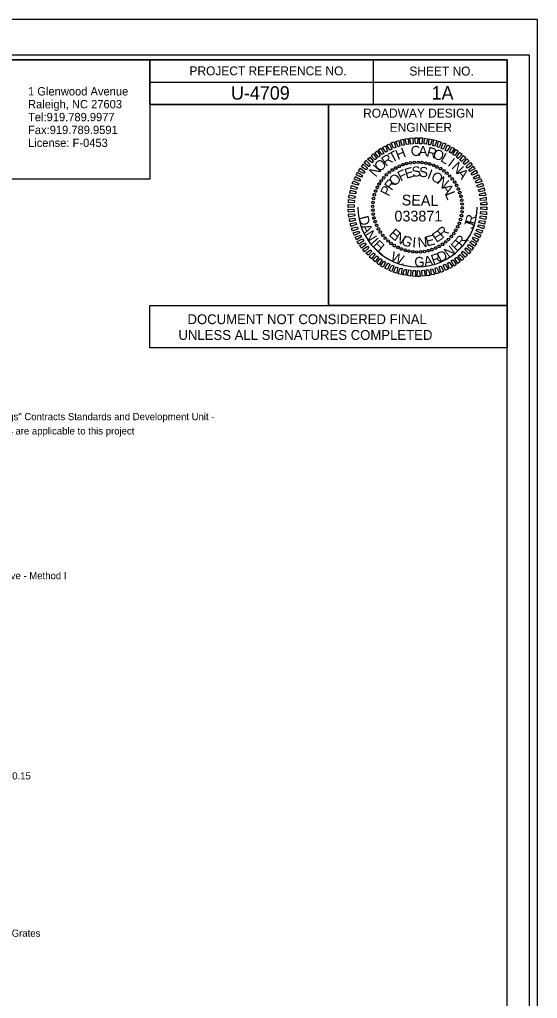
# Model space of a CAD drawing. Extents: x 1537922 to 1539606, y 409903 to 410998.
# Drawn here: x 1539316 to 1539606, y 410451 to 410998 of the extents above; entities that cross this region are included whole.
import ezdxf

# ---------------------------------------------------------------- set-up
doc = ezdxf.new("R2010")
doc.units = 0
for name, color, linetype in [('Old_Level_1', 7, 'Continuous'), ('Old_Level_2', 7, 'Continuous'), ('Old_Level_58', 7, 'Continuous'), ('Scratch_Level_0', 7, 'Continuous'), ('Sheet Cutting Line CELL', 7, 'Continuous'), ('Sheet Data Field CELL', 7, 'Continuous'), ('Sheet Plan CELL', 7, 'Continuous'), ('Sheet Plot Border Inside CELL', 7, 'Continuous'), ('Sheet Plot Border Outside CELL', 7, 'Continuous'), ('Sheet Professional Seal CELL', 7, 'Continuous'), ('Sheet Profile Grid Minor CELL', 7, 'Continuous'), ('Sheet Sticker Exception Certification CELL', 7, 'Continuous')]:
    doc.layers.add(name, color=color, linetype=linetype)

msp = doc.modelspace()

# ---------------------------------------------------------------- linework, layer by layer
at = {"layer": 'Old_Level_58'}
msp.add_lwpolyline([(1539188.77, 410975.85), (1539388.82, 410975.85), (1539388.82, 410909.16), (1539188.77, 410909.16)], close=True, dxfattribs=at)
at = {"layer": 'Scratch_Level_0'}
msp.add_arc((1539538.69, 410893.42), 33.36, 180, 360, dxfattribs=at)
at = {"layer": 'Sheet Cutting Line CELL'}
msp.add_line((1539605.87, 410998.35), (1537922.37, 410998.35), dxfattribs=at)
at = {"layer": 'Sheet Plan CELL'}
for p, q in [((1539513.87, 410975.8), (1539513.87, 410950.8)), ((1539388.82, 410963.3), (1539588.87, 410963.3)), ((1539388.82, 410950.8), (1539588.87, 410950.8)), ((1539388.82, 410950.8), (1539588.87, 410950.8)), ((1539488.87, 410950.8), (1539488.87, 410838.35))]:
    msp.add_line(p, q, dxfattribs=at)
for points in [[(1539588.87, 410975.85), (1538088.87, 410975.85), (1538088.87, 409925.85), (1539588.87, 409925.85)], [(1539388.82, 410975.85), (1539588.87, 410975.85), (1539588.87, 410950.8), (1539388.82, 410950.8)], [(1539488.87, 410950.8), (1539588.87, 410950.8), (1539588.87, 410838.3), (1539488.87, 410838.3)]]:
    msp.add_lwpolyline(points, close=True, dxfattribs=at)
at = {"layer": 'Sheet Plot Border Inside CELL'}
msp.add_lwpolyline([(1537935.37, 409923.35), (1539601.37, 409923.35), (1539601.37, 410978.35), (1537935.37, 410978.35)], close=True, dxfattribs=at)
at = {"layer": 'Sheet Plot Border Outside CELL'}
msp.add_lwpolyline([(1537922.37, 409903.35), (1539605.87, 409903.35), (1539605.87, 410998.35), (1537922.37, 410998.35)], close=True, dxfattribs=at)
at = {"layer": 'Sheet Professional Seal CELL'}
for p, q in [((1539528.49, 410916.37), (1539528.49, 410916.37)), ((1539530.49, 410917.17), (1539530.49, 410917.17)), ((1539532.59, 410917.77), (1539532.59, 410917.77)), ((1539534.79, 410918.17), (1539534.79, 410918.17)), ((1539536.94, 410918.47), (1539536.94, 410918.47)), ((1539539.14, 410918.52), (1539539.14, 410918.52)), ((1539541.34, 410918.37), (1539541.34, 410918.37)), ((1539543.49, 410918.02), (1539543.49, 410918.02)), ((1539545.59, 410917.57), (1539545.59, 410917.57)), ((1539547.69, 410916.87), (1539547.69, 410916.87)), ((1539549.69, 410915.97), (1539549.69, 410915.97)), ((1539521.24, 410911.47), (1539521.24, 410911.47)), ((1539522.89, 410912.97), (1539522.89, 410912.97)), ((1539524.64, 410914.22), (1539524.64, 410914.22)), ((1539526.54, 410915.37), (1539526.54, 410915.37)), ((1539551.64, 410914.97), (1539551.64, 410914.97)), ((1539553.44, 410913.72), (1539553.44, 410913.72)), ((1539555.19, 410912.37), (1539555.19, 410912.37)), ((1539556.74, 410910.87), (1539556.74, 410910.87)), ((1539517.14, 410906.37), (1539517.14, 410906.37)), ((1539518.39, 410908.17), (1539518.39, 410908.17)), ((1539519.74, 410909.92), (1539519.74, 410909.92)), ((1539558.24, 410909.22), (1539558.24, 410909.22)), ((1539559.49, 410907.47), (1539559.49, 410907.47)), ((1539560.64, 410905.57), (1539560.64, 410905.57)), ((1539514.54, 410900.32), (1539514.54, 410900.32)), ((1539515.24, 410902.42), (1539515.24, 410902.42)), ((1539516.14, 410904.42), (1539516.14, 410904.42)), ((1539561.64, 410903.62), (1539561.64, 410903.62)), ((1539562.44, 410901.62), (1539562.44, 410901.62)), ((1539563.04, 410899.52), (1539563.04, 410899.52)), ((1539513.59, 410893.87), (1539513.59, 410893.87)), ((1539513.74, 410896.07), (1539513.74, 410896.07)), ((1539514.09, 410898.22), (1539514.09, 410898.22)), ((1539563.44, 410897.32), (1539563.44, 410897.32)), ((1539563.74, 410895.17), (1539563.74, 410895.17)), ((1539513.64, 410891.67), (1539513.64, 410891.67)), ((1539513.94, 410889.52), (1539513.94, 410889.52)), ((1539538.69, 410893.42), (1539538.69, 410893.42)), ((1539563.29, 410888.62), (1539563.29, 410888.62)), ((1539563.64, 410890.77), (1539563.64, 410890.77)), ((1539563.79, 410892.97), (1539563.79, 410892.97)), ((1539514.34, 410887.32), (1539514.34, 410887.32)), ((1539514.94, 410885.22), (1539514.94, 410885.22)), ((1539515.74, 410883.22), (1539515.74, 410883.22)), ((1539562.14, 410884.42), (1539562.14, 410884.42)), ((1539562.84, 410886.52), (1539562.84, 410886.52)), ((1539516.74, 410881.27), (1539516.74, 410881.27)), ((1539517.89, 410879.37), (1539517.89, 410879.37)), ((1539519.14, 410877.62), (1539519.14, 410877.62)), ((1539558.99, 410878.67), (1539558.99, 410878.67)), ((1539560.24, 410880.47), (1539560.24, 410880.47)), ((1539561.24, 410882.42), (1539561.24, 410882.42)), ((1539520.64, 410875.97), (1539520.64, 410875.97)), ((1539522.19, 410874.47), (1539522.19, 410874.47)), ((1539523.94, 410873.12), (1539523.94, 410873.12)), ((1539525.74, 410871.87), (1539525.74, 410871.87)), ((1539552.74, 410872.62), (1539552.74, 410872.62)), ((1539554.49, 410873.87), (1539554.49, 410873.87)), ((1539556.14, 410875.37), (1539556.14, 410875.37)), ((1539557.64, 410876.92), (1539557.64, 410876.92)), ((1539527.69, 410870.87), (1539527.69, 410870.87)), ((1539529.69, 410869.97), (1539529.69, 410869.97)), ((1539531.79, 410869.27), (1539531.79, 410869.27)), ((1539533.89, 410868.82), (1539533.89, 410868.82)), ((1539536.04, 410868.47), (1539536.04, 410868.47)), ((1539538.24, 410868.32), (1539538.24, 410868.32)), ((1539540.44, 410868.37), (1539540.44, 410868.37)), ((1539542.59, 410868.67), (1539542.59, 410868.67)), ((1539544.79, 410869.07), (1539544.79, 410869.07)), ((1539546.89, 410869.67), (1539546.89, 410869.67)), ((1539548.89, 410870.47), (1539548.89, 410870.47)), ((1539550.84, 410871.47), (1539550.84, 410871.47))]:
    msp.add_line(p, q, dxfattribs=at)
for points in [[(1539534.99, 410928.72), (1539534.44, 410931.92), (1539536.14, 410932.12), (1539536.19, 410928.87)], [(1539537.49, 410928.97), (1539537.24, 410932.22), (1539538.89, 410932.17), (1539538.69, 410928.92)], [(1539539.89, 410928.92), (1539539.89, 410932.17), (1539541.54, 410932.12), (1539541.09, 410928.87)], [(1539542.39, 410928.77), (1539542.59, 410932.02), (1539544.24, 410931.72), (1539543.59, 410928.57)], [(1539520.99, 410924.17), (1539519.14, 410926.87), (1539520.69, 410927.67), (1539521.94, 410924.77)], [(1539523.14, 410925.37), (1539521.54, 410928.17), (1539523.09, 410928.87), (1539524.24, 410925.82)], [(1539525.34, 410926.42), (1539524.04, 410929.32), (1539525.54, 410929.92), (1539526.59, 410926.72)], [(1539527.79, 410927.22), (1539526.64, 410930.22), (1539528.19, 410930.67), (1539528.84, 410927.57)], [(1539530.19, 410927.87), (1539529.14, 410931.02), (1539530.84, 410931.37), (1539531.24, 410928.12)], [(1539532.59, 410928.42), (1539531.79, 410931.62), (1539533.44, 410931.77), (1539533.79, 410928.57)], [(1539544.79, 410928.37), (1539545.24, 410931.57), (1539546.89, 410931.32), (1539545.99, 410928.22)], [(1539547.34, 410927.82), (1539547.84, 410931.07), (1539549.54, 410930.67), (1539548.39, 410927.57)], [(1539549.74, 410927.17), (1539550.49, 410930.27), (1539552.04, 410929.77), (1539550.79, 410926.82)], [(1539551.99, 410926.27), (1539553.14, 410929.42), (1539554.54, 410928.82), (1539553.14, 410925.92)], [(1539554.24, 410925.32), (1539555.49, 410928.27), (1539557.04, 410927.57), (1539555.34, 410924.77)], [(1539556.54, 410924.17), (1539557.89, 410927.02), (1539559.39, 410926.17), (1539557.49, 410923.57)], [(1539513.24, 410918.12), (1539510.69, 410920.17), (1539511.94, 410921.32), (1539514.04, 410918.92)], [(1539514.89, 410919.87), (1539512.69, 410922.07), (1539513.89, 410923.27), (1539515.84, 410920.57)], [(1539516.89, 410921.42), (1539514.74, 410923.82), (1539516.09, 410924.87), (1539517.84, 410922.07)], [(1539518.79, 410922.92), (1539516.94, 410925.47), (1539518.24, 410926.42), (1539519.89, 410923.52)], [(1539558.49, 410922.82), (1539560.24, 410925.72), (1539561.54, 410924.67), (1539559.59, 410922.22)], [(1539560.54, 410921.32), (1539562.39, 410924.07), (1539563.69, 410922.97), (1539561.49, 410920.62)], [(1539562.44, 410919.77), (1539564.49, 410922.37), (1539565.69, 410921.17), (1539563.39, 410919.02)], [(1539509.99, 410914.32), (1539507.29, 410916.02), (1539508.24, 410917.47), (1539510.64, 410915.27)], [(1539511.49, 410916.22), (1539508.89, 410918.17), (1539509.99, 410919.47), (1539512.19, 410917.12)], [(1539564.24, 410918.02), (1539566.39, 410920.37), (1539567.59, 410919.17), (1539564.99, 410917.22)], [(1539565.99, 410916.22), (1539568.29, 410918.47), (1539569.34, 410917.12), (1539566.69, 410915.22)], [(1539567.49, 410914.27), (1539569.94, 410916.37), (1539570.89, 410914.92), (1539568.09, 410913.32)], [(1539506.29, 410907.87), (1539503.19, 410909.02), (1539503.94, 410910.57), (1539506.79, 410908.97)], [(1539507.29, 410910.17), (1539504.44, 410911.42), (1539505.19, 410912.97), (1539507.89, 410911.12)], [(1539508.49, 410912.32), (1539505.69, 410913.82), (1539506.69, 410915.22), (1539509.29, 410913.22)], [(1539568.79, 410912.22), (1539571.44, 410914.12), (1539572.39, 410912.62), (1539569.49, 410911.22)], [(1539570.09, 410910.02), (1539572.89, 410911.77), (1539573.54, 410910.22), (1539570.69, 410909.07)], [(1539504.54, 410903.27), (1539501.44, 410903.92), (1539501.79, 410905.57), (1539504.94, 410904.32)], [(1539505.29, 410905.67), (1539502.19, 410906.57), (1539502.84, 410908.12), (1539505.84, 410906.72)], [(1539571.09, 410907.87), (1539574.04, 410909.37), (1539574.69, 410907.77), (1539571.59, 410906.77)], [(1539571.99, 410905.52), (1539575.04, 410906.82), (1539575.59, 410905.27), (1539572.49, 410904.47)], [(1539503.49, 410898.32), (1539500.29, 410898.62), (1539500.49, 410900.32), (1539503.74, 410899.52)], [(1539503.89, 410900.87), (1539500.79, 410901.27), (1539501.14, 410902.97), (1539504.29, 410901.92)], [(1539572.79, 410903.12), (1539575.99, 410904.27), (1539576.29, 410902.62), (1539573.14, 410902.07)], [(1539573.39, 410900.72), (1539576.54, 410901.67), (1539576.84, 410899.97), (1539573.69, 410899.67)], [(1539503.19, 410893.42), (1539499.94, 410893.27), (1539499.94, 410894.97), (1539503.19, 410894.62)], [(1539503.24, 410895.92), (1539499.99, 410896.02), (1539500.09, 410897.67), (1539503.34, 410897.12)], [(1539573.84, 410898.32), (1539577.09, 410899.02), (1539577.24, 410897.32), (1539574.04, 410897.12)], [(1539574.14, 410895.92), (1539577.39, 410896.32), (1539577.49, 410894.62), (1539574.24, 410894.72)], [(1539503.24, 410890.92), (1539499.99, 410890.52), (1539499.89, 410892.22), (1539503.14, 410892.12)], [(1539503.54, 410888.52), (1539500.29, 410887.82), (1539500.14, 410889.52), (1539503.34, 410889.72)], [(1539573.89, 410888.52), (1539577.09, 410888.22), (1539576.89, 410886.52), (1539573.64, 410887.32)], [(1539574.14, 410890.92), (1539577.39, 410890.82), (1539577.29, 410889.17), (1539574.04, 410889.72)], [(1539574.19, 410893.42), (1539577.44, 410893.57), (1539577.44, 410891.87), (1539574.19, 410892.22)], [(1539503.99, 410886.12), (1539500.84, 410885.17), (1539500.54, 410886.87), (1539503.69, 410887.17)], [(1539504.59, 410883.72), (1539501.39, 410882.57), (1539501.09, 410884.22), (1539504.24, 410884.77)], [(1539572.84, 410883.57), (1539575.94, 410882.92), (1539575.59, 410881.27), (1539572.44, 410882.52)], [(1539573.49, 410885.97), (1539576.59, 410885.57), (1539576.24, 410883.87), (1539573.09, 410884.92)], [(1539505.39, 410881.32), (1539502.34, 410880.02), (1539501.79, 410881.57), (1539504.89, 410882.37)], [(1539506.29, 410878.97), (1539503.34, 410877.47), (1539502.69, 410879.07), (1539505.79, 410880.07)], [(1539507.29, 410876.82), (1539504.49, 410875.07), (1539503.84, 410876.62), (1539506.69, 410877.77)], [(1539571.09, 410878.97), (1539574.19, 410877.82), (1539573.44, 410876.27), (1539570.59, 410877.87)], [(1539572.09, 410881.17), (1539575.19, 410880.27), (1539574.54, 410878.72), (1539571.54, 410880.12)], [(1539508.59, 410874.62), (1539505.94, 410872.72), (1539504.99, 410874.22), (1539507.89, 410875.62)], [(1539509.89, 410872.57), (1539507.44, 410870.47), (1539506.49, 410871.92), (1539509.29, 410873.52)], [(1539567.39, 410872.52), (1539570.09, 410870.82), (1539569.14, 410869.37), (1539566.74, 410871.57)], [(1539568.89, 410874.52), (1539571.69, 410873.02), (1539570.69, 410871.62), (1539568.09, 410873.62)], [(1539570.09, 410876.67), (1539572.94, 410875.42), (1539572.19, 410873.87), (1539569.49, 410875.72)], [(1539511.39, 410870.62), (1539509.09, 410868.37), (1539508.04, 410869.72), (1539510.69, 410871.62)], [(1539513.14, 410868.82), (1539510.99, 410866.47), (1539509.79, 410867.67), (1539512.39, 410869.62)], [(1539514.94, 410867.07), (1539512.89, 410864.47), (1539511.69, 410865.67), (1539513.99, 410867.82)], [(1539562.49, 410866.97), (1539564.69, 410864.77), (1539563.49, 410863.57), (1539561.54, 410866.27)], [(1539564.14, 410868.72), (1539566.69, 410866.67), (1539565.44, 410865.52), (1539563.34, 410867.92)], [(1539565.89, 410870.62), (1539568.49, 410868.67), (1539567.39, 410867.37), (1539565.19, 410869.72)], [(1539516.84, 410865.52), (1539514.99, 410862.77), (1539513.69, 410863.87), (1539515.89, 410866.22)], [(1539518.89, 410864.02), (1539517.14, 410861.12), (1539515.84, 410862.17), (1539517.79, 410864.62)], [(1539520.84, 410862.67), (1539519.49, 410859.82), (1539517.99, 410860.67), (1539519.89, 410863.27)], [(1539523.14, 410861.52), (1539521.89, 410858.57), (1539520.34, 410859.27), (1539522.04, 410862.07)], [(1539525.39, 410860.57), (1539524.24, 410857.42), (1539522.84, 410858.02), (1539524.24, 410860.92)], [(1539554.24, 410861.47), (1539555.84, 410858.67), (1539554.29, 410857.97), (1539553.14, 410861.02)], [(1539556.39, 410862.67), (1539558.24, 410859.97), (1539556.69, 410859.17), (1539555.44, 410862.07)], [(1539558.59, 410863.92), (1539560.44, 410861.37), (1539559.14, 410860.42), (1539557.49, 410863.32)], [(1539560.49, 410865.42), (1539562.64, 410863.02), (1539561.29, 410861.97), (1539559.54, 410864.77)], [(1539527.64, 410859.67), (1539526.89, 410856.57), (1539525.34, 410857.07), (1539526.59, 410860.02)], [(1539530.04, 410859.02), (1539529.54, 410855.77), (1539527.84, 410856.17), (1539528.99, 410859.27)], [(1539532.59, 410858.47), (1539532.14, 410855.27), (1539530.49, 410855.52), (1539531.39, 410858.62)], [(1539534.99, 410858.07), (1539534.79, 410854.82), (1539533.14, 410855.12), (1539533.79, 410858.27)], [(1539537.49, 410857.92), (1539537.49, 410854.67), (1539535.84, 410854.72), (1539536.29, 410857.97)], [(1539539.89, 410857.87), (1539540.14, 410854.62), (1539538.49, 410854.67), (1539538.69, 410857.92)], [(1539542.39, 410858.12), (1539542.94, 410854.92), (1539541.24, 410854.72), (1539541.19, 410857.97)], [(1539544.79, 410858.42), (1539545.59, 410855.22), (1539543.94, 410855.07), (1539543.59, 410858.27)], [(1539547.19, 410858.97), (1539548.24, 410855.82), (1539546.54, 410855.47), (1539546.14, 410858.72)], [(1539549.59, 410859.62), (1539550.74, 410856.62), (1539549.19, 410856.17), (1539548.54, 410859.27)], [(1539552.04, 410860.42), (1539553.34, 410857.52), (1539551.84, 410856.92), (1539550.79, 410860.12)]]:
    msp.add_lwpolyline(points, close=True, dxfattribs=at)
for centre, major_axis in [((1539526.53, 410915.36), (-0.349, 0.63)), ((1539528.49, 410916.33), (-0.293, 0.658)), ((1539530.52, 410917.13), (-0.234, 0.681)), ((1539532.62, 410917.76), (-0.174, 0.699)), ((1539534.77, 410918.19), (-0.113, 0.711)), ((1539536.94, 410918.44), (-0.05, 0.718)), ((1539539.13, 410918.5), (0.013, 0.72)), ((1539541.31, 410918.36), (0.075, 0.716)), ((1539543.48, 410918.04), (0.137, 0.707)), ((1539545.6, 410917.53), (0.198, 0.692)), ((1539547.68, 410916.84), (0.258, 0.672)), ((1539549.68, 410915.96), (0.316, 0.647)), ((1539551.61, 410914.92), (0.371, 0.617)), ((1539519.76, 410909.88), (-0.543, 0.472)), ((1539521.27, 410911.46), (-0.5, 0.518)), ((1539522.91, 410912.91), (-0.453, 0.56)), ((1539524.67, 410914.21), (-0.403, 0.597)), ((1539553.43, 410913.71), (0.423, 0.582)), ((1539555.14, 410912.35), (0.472, 0.543)), ((1539556.73, 410910.84), (0.518, 0.5)), ((1539516.15, 410904.42), (-0.647, 0.316)), ((1539517.19, 410906.34), (-0.617, 0.371)), ((1539518.4, 410908.16), (-0.582, 0.423)), ((1539558.18, 410909.2), (0.56, 0.453)), ((1539559.48, 410907.45), (0.597, 0.403)), ((1539560.63, 410905.58), (0.63, 0.349)), ((1539514.58, 410900.33), (-0.692, 0.198)), ((1539515.28, 410902.41), (-0.672, 0.258)), ((1539561.6, 410903.62), (0.658, 0.293)), ((1539562.4, 410901.59), (0.681, 0.234)), ((1539563.02, 410899.49), (0.699, 0.174)), ((1539513.61, 410893.86), (-0.72, 0.013)), ((1539513.75, 410896.04), (-0.716, 0.075)), ((1539514.07, 410898.21), (-0.707, 0.137)), ((1539563.46, 410897.34), (0.711, 0.113)), ((1539563.71, 410895.17), (0.718, 0.05)), ((1539563.77, 410892.98), (0.72, -0.013)), ((1539513.67, 410891.67), (-0.718, -0.05)), ((1539513.92, 410889.5), (-0.711, -0.113)), ((1539563.31, 410888.64), (0.707, -0.137)), ((1539563.63, 410890.8), (0.716, -0.075)), ((1539514.35, 410887.35), (-0.699, -0.174)), ((1539514.98, 410885.26), (-0.681, -0.234)), ((1539515.78, 410883.22), (-0.658, -0.293)), ((1539561.23, 410882.43), (0.647, -0.316)), ((1539562.1, 410884.43), (0.672, -0.258)), ((1539562.8, 410886.51), (0.692, -0.198)), ((1539516.75, 410881.26), (-0.63, -0.349)), ((1539517.9, 410879.4), (-0.597, -0.403)), ((1539519.2, 410877.64), (-0.56, -0.453)), ((1539557.62, 410876.97), (0.543, -0.472)), ((1539558.98, 410878.68), (0.582, -0.423)), ((1539560.19, 410880.5), (0.617, -0.371)), ((1539520.65, 410876), (-0.518, -0.5)), ((1539522.24, 410874.49), (-0.472, -0.543)), ((1539523.95, 410873.13), (-0.423, -0.582)), ((1539525.77, 410871.92), (-0.371, -0.617)), ((1539550.85, 410871.49), (0.349, -0.63)), ((1539552.71, 410872.63), (0.403, -0.597)), ((1539554.47, 410873.93), (0.453, -0.56)), ((1539556.11, 410875.38), (0.5, -0.518)), ((1539527.7, 410870.88), (-0.316, -0.647)), ((1539529.7, 410870.01), (-0.258, -0.672)), ((1539531.78, 410869.31), (-0.198, -0.692)), ((1539533.9, 410868.8), (-0.137, -0.707)), ((1539536.07, 410868.48), (-0.075, -0.716)), ((1539538.25, 410868.34), (-0.013, -0.72)), ((1539540.44, 410868.4), (0.05, -0.718)), ((1539542.61, 410868.65), (0.113, -0.711)), ((1539544.76, 410869.09), (0.174, -0.699)), ((1539546.85, 410869.71), (0.234, -0.681)), ((1539548.89, 410870.51), (0.293, -0.658))]:
    msp.add_ellipse(centre, major_axis=major_axis, ratio=0.999708, dxfattribs=at)
at = {"layer": 'Sheet Sticker Exception Certification CELL'}
for p, q in [((1539388.83, 410814.8), (1539388.83, 410838.3)), ((1539388.83, 410838.3), (1539588.87, 410838.3)), ((1539588.87, 410838.29), (1539588.87, 410814.79)), ((1539588.87, 410814.8), (1539388.83, 410814.8))]:
    msp.add_line(p, q, dxfattribs=at)

# ---------------------------------------------------------------- texts
at = {"layer": 'Old_Level_1'}
for s, p in [('The following Roadway Standards as appear in "Roadway Standard Drawings" Contracts Standards and Development Unit -', (1539130.41, 410774.24)), ('N. C. Department of Transportation - Raleigh, N. C., Dated January 16, 2024 are applicable to this project', (1539130.41, 410766.24)), ('560.01    Method of Shoulder Construction - High Side of Superelevated Curve - Method I', (1539130.41, 410685.27)), ('840.16    Drop Inlet Frame and Grates - for use with Std. Dwg 840.14 and 840.15', (1539130.41, 410573.24)), ('840.35    Traffic Bearing Grated Drop Inlet - for Cast Iron Double Frame and Grates', (1539130.41, 410485.24))]:
    msp.add_text(s, height=4, dxfattribs=at).set_placement(p)
at = {"layer": 'Old_Level_2'}
for s, p in [('1 Glenwood Avenue', (1539320.61, 410955.89)), ('Raleigh, NC 27603', (1539320.61, 410948.69)), ('Tel:919.789.9977 ', (1539320.61, 410941.49)), ('Fax:919.789.9591', (1539320.61, 410934.3)), ('License: F-0453', (1539320.61, 410927.1))]:
    msp.add_text(s, height=4.6576, rotation=360, dxfattribs=at).set_placement(p)
at = {"layer": 'Sheet Data Field CELL'}
for s, p in [('U-4709', (1539434.25, 410953.55)), ('1A', (1539546.58, 410953.6))]:
    msp.add_text(s, height=7.5, dxfattribs=at).set_placement(p)
at = {"layer": 'Sheet Plan CELL'}
for s, height, p in [('PROJECT REFERENCE NO.', 5.0001, (1539411.02, 410967.15)), ('SHEET NO.', 5, (1539534.17, 410967.05)), ('ROADWAY DESIGN', 5.0001, (1539508.27, 410943.5)), ('ENGINEER', 5, (1539523.12, 410935.55))]:
    msp.add_text(s, height=height, dxfattribs=at).set_placement(p)
at = {"layer": 'Sheet Professional Seal CELL'}
for s, height, rotation, p in [('H', 5.64, 20.6195, (1539527.64, 410919.77)), ('C', 5.64, 6.2199, (1539535.24, 410921.77)), ('A', 5.64, 359.0203, (1539539.19, 410922.07)), ('R', 5.64, 344.6211, (1539543.39, 410921.87)), ('R', 5.64, 35.0205, (1539520.99, 410915.92)), ('T', 5.64, 27.8198, (1539524.39, 410918.12)), ('O', 5.64, 337.4212, (1539546.74, 410921.12)), ('L', 5.64, 330.2209, (1539551.14, 410919.27)), ('N', 5.64, 49.4235, (1539515.24, 410909.92)), ('O', 5.64, 42.2217, (1539517.54, 410912.82)), ('E', 5.64, 16.6111, (1539532.44, 410909.22)), ('S', 5.64, 7.2556, (1539535.89, 410910.27)), ('S', 5.64, 357.9004, (1539539.49, 410910.32)), ('I', 5.64, 323.0201, (1539555.19, 410916.87)), ('N', 5.64, 315.8189, (1539557.34, 410915.32)), ('O', 5.64, 44.6812, (1539525.94, 410904.77)), ('F', 5.64, 25.967, (1539529.24, 410907.72)), ('I', 5.64, 339.1896, (1539543.79, 410909.62)), ('O', 5.64, 329.8335, (1539545.79, 410908.92)), ('N', 5.64, 320.4766, (1539549.14, 410906.92)), ('A', 5.64, 308.6172, (1539560.29, 410912.37)), ('P', 5.64, 63.3989, (1539522.59, 410899.12)), ('R', 5.64, 54.0397, (1539524.19, 410902.32)), ('A', 5.64, 301.7603, (1539551.99, 410904.32)), ('SEAL', 5.998, 359, (1539529.84, 410894.42)), ('L', 5.64, 292.4008, (1539553.94, 410900.87)), ('E', 5.64, 318.2769, (1539522.29, 410877.77)), ('N', 5.64, 327.634, (1539525.29, 410875.07)), ('G', 5.64, 336.9902, (1539529.09, 410872.82)), ('E', 5.64, 14.4118, (1539543.94, 410871.37)), ('E', 5.64, 33.1241, (1539549.24, 410873.32)), ('R', 5.64, 42.4814, (1539552.79, 410875.67)), ('I', 5.64, 355.7012, (1539535.64, 410870.92)), ('N', 5.64, 5.0564, (1539538.99, 410870.77))]:
    msp.add_text(s, height=height, rotation=rotation, dxfattribs=at).set_placement(p)
at = {"layer": 'Sheet Profile Grid Minor CELL'}
for s, rotation, p in [('D', 284.2682, (1539505.7, 410887.78)), ('R', 77.3541, (1539570.66, 410883.52)), ('.', 84.2805, (1539571.62, 410887.45)), ('A', 293.4128, (1539507.01, 410882.61)), ('J', 72.4855, (1539569.71, 410880.84)), ('N', 301.5986, (1539508.88, 410878.21)), ('R', 52.3788, (1539563.49, 410870.95)), ('I', 311.5304, (1539511.95, 410873.29)), ('E', 315.0508, (1539513.23, 410871.69)), ('L', 321.6338, (1539515.89, 410868.91)), ('N', 35.8641, (1539556.08, 410864.82)), ('E', 45.7958, (1539560.75, 410868.25)), (',', 59.3052, (1539566.02, 410874.1)), ('W', 336.8891, (1539523.15, 410863.78)), ('R', 19.793, (1539547.48, 410861.13)), ('D', 26.7195, (1539551.31, 410862.42)), ('.', 348.4952, (1539529.43, 410861.26)), ('G', 1.6755, (1539537, 410859.99)), ('A', 11.6072, (1539542.79, 410860.2))]:
    msp.add_text(s, height=5.5, rotation=rotation, dxfattribs=at).set_placement(p)
msp.add_text('033871', height=5.998, dxfattribs=at).set_placement((1539525.79, 410885.41))
at = {"layer": 'Sheet Sticker Exception Certification CELL'}
for s, p in [('DOCUMENT NOT CONSIDERED FINAL', (1539409.9, 410827.96)), ('UNLESS ALL SIGNATURES COMPLETED', (1539404.83, 410819.16))]:
    msp.add_text(s, height=5.5, dxfattribs=at).set_placement(p)

doc.saveas('drawing.dxf')
